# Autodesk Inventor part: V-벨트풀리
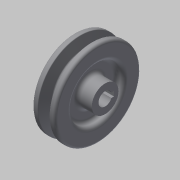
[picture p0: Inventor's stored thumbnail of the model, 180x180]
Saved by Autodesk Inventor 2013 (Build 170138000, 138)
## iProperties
Created: 2015-02
Part Number: V-벨트풀리
Material: 일반
Document SubType Name: Modeling
Designer: Administrator
Density: 1 g/cm^3
Author: Administrator
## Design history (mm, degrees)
sketch "스케치1"
  geometry: L1 (-12.5, 0)-(12.5, 0); L2 (-12.5, 5.5)-(12.5, 5.5); L3 (12.5, 5.5)-(12.5, 11); L4 (12.5, 11)-(0.5, 11); L5 (0.5, 11)-(0.5, 21.5); L6 (0.5, 21.5)-(6.5, 21.5); L7 (6.5, 21.5)-(6.5, 35.2); L8 (-12.5, 35.2)-(-12.5, 21.5); L9 (-12.5, 21.5)-(-6.5, 21.5); L10 (-6.5, 21.5)-(-6.5, 11); L11 (-6.5, 11)-(-12.5, 11); L12 (-12.5, 11)-(-12.5, 5.5); L13 (-5.074, 26.2)-(-0.926, 26.2); L14 (-7, 32.5)-(1, 32.5); L15 (-12.5, 35.2)-(-7.825, 35.2); L16 (1.825, 35.2)-(6.5, 35.2); L17 (1.825, 35.2)-(-0.926, 26.2); L18 (-7.825, 35.2)-(-5.074, 26.2); 5 further points
  constraints: 36 end point, 10 parallel, 3 collinear, 3 equal length, 3 midpoint, 3 perpendicular, 3 point on line, 3 vertical alignment, 1 coincident, 1 horizontal
  dimensions: "d0" = 25 distance of L1.start L1.end; "d2" = 11 diameter of L2 L1; "d3" = 22 diameter of L4 L1; "d4" = 6 distance between parallel lines of L10 L12; "d5" = 19 distance between parallel lines of L7 L8; "d6" = 43 diameter of L9 L1; "d11" = 65 diameter of L14 L1; "d12" = 6.3 distance between parallel lines of L13 L14; "d14" = 2.7 distance between parallel lines of L14 L16; "d15" = 34 deg angle of L18 L17; "d16" = 8 distance of L14.end L14.start
revolve "회전1" sketch "스케치1" stored, may be unused: angle "d17" = 90 deg
sketch "스케치2"
  geometry: L1 (-12.5, 2)-(12.5, 2); L2 (12.5, 2)-(12.5, -2); L3 (12.5, -2)-(-12.5, -2); L4 (-12.5, -2)-(-12.5, 2); L5 (-12.5, 5.5)-(-12.5, -5.5) reference; L6 (12.5, 5.5)-(12.5, -5.5) reference; L7 (-12.5, 5.5)-(12.5, 5.5) reference; L8 (-12.5, -5.5)-(12.5, -5.5) reference; 3 further points
  constraints: 8 end point, 3 midpoint, 2 parallel, 1 horizontal, 1 horizontal alignment, 1 perpendicular, 1 vertical alignment
  dimensions: "d18" = 4 distance of L1.end L2.end
extrude "돌출1" cut sketch "스케치2" distance "d20" = 7.3; taper "d21" = 0 deg
fillet "모깎기1" dims "d22" = 2, "d23" = 0.5, "d24" = 1
fillet "모깎기2" dims "d25" = 3
fillet "모깎기3" dims "d26" = 3
fillet "모깎기4" dims "d27" = 3
node "솔리드1"
other parameters: "d13" = 2.7
